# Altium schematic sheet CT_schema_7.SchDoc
size 274 x 160 mm
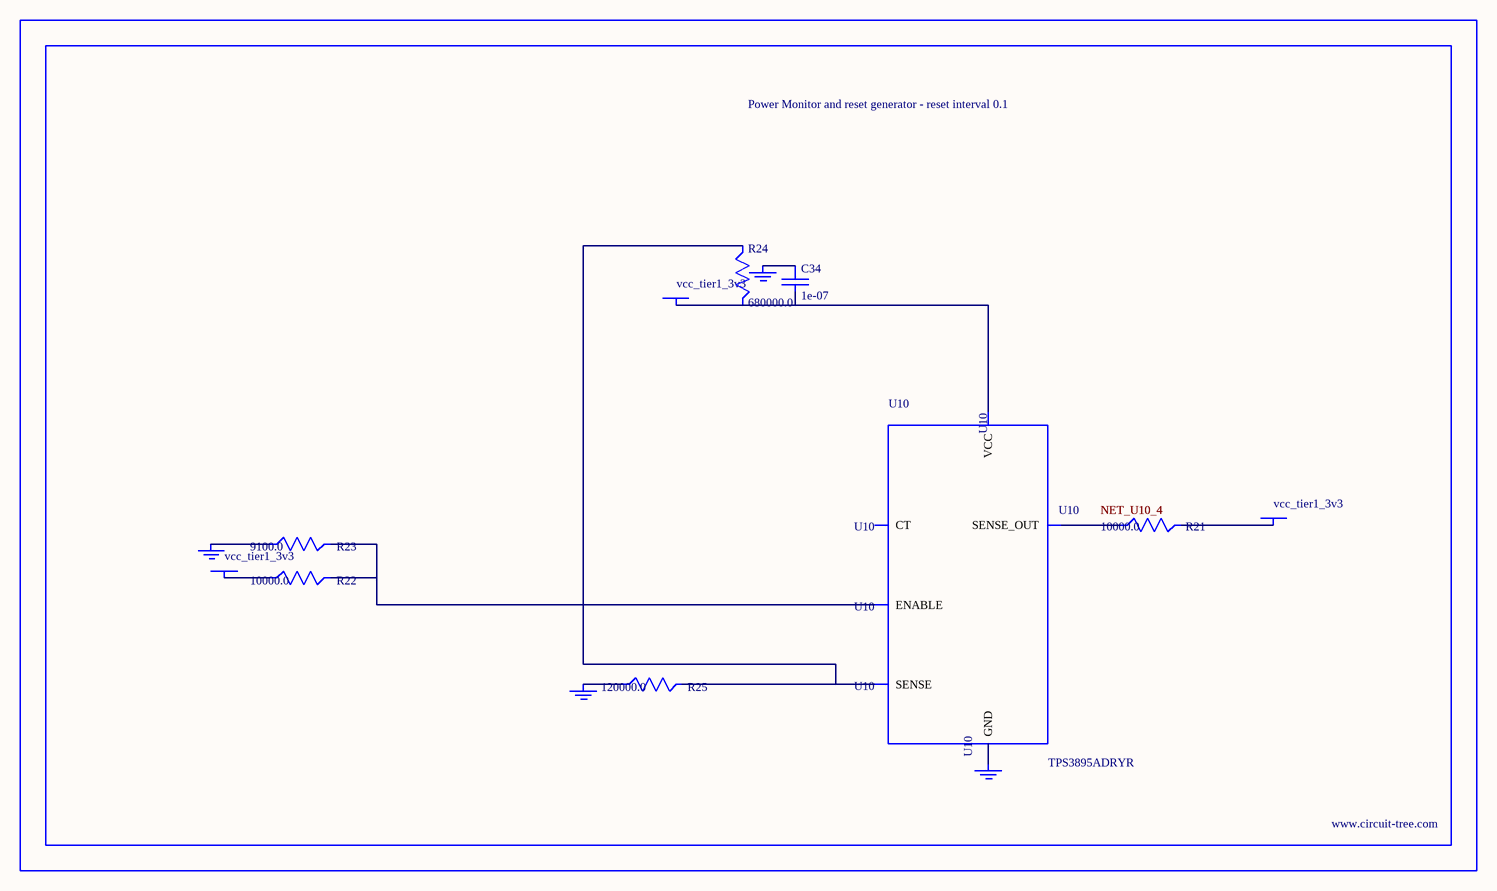
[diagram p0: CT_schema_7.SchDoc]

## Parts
BORDER6  (no value)
C34  1e-07  [C0402]
GND_INSTANCE_6_0  (no value)
GND_INSTANCE_6_1  (no value)
GND_INSTANCE_6_2  (no value)
GND_INSTANCE_6_3  (no value)
POWER_INSTANCE_6_0  vcc_tier1_3v3
POWER_INSTANCE_6_1  vcc_tier1_3v3
POWER_INSTANCE_6_2  vcc_tier1_3v3
R21  10000.0  [R0603]
R22  10000.0  [R0603]
R23  9100.0  [R0603]
R24  680000.0  [R0603]
R25  120000.0  [R0603]
U10  TPS3895ADRYR  [SON-6]

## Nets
NetC34_1: C34.1 GND_INSTANCE_6_2.0(GND)
NetC34_2: C34.2 POWER_INSTANCE_6_2.0(PWR) R24.2 U10.6(VCC)
NetGND_INSTANCE_6_0_0: GND_INSTANCE_6_0.0(GND) R23.1
NetGND_INSTANCE_6_1_0: GND_INSTANCE_6_1.0(GND) R25.1
NetGND_INSTANCE_6_3_0: GND_INSTANCE_6_3.0(GND) U10.2(GND)
NetPOWER_INSTANCE_6_0_0: POWER_INSTANCE_6_0.0(PWR) R22.1
NetPOWER_INSTANCE_6_1_0: POWER_INSTANCE_6_1.0(PWR) R21.2
NetR21_1: R21.1 U10.4(SENSE_OUT)
NetR22_2: R22.2 R23.2 U10.1(ENABLE)
NetR24_1: R24.1 R25.2 U10.3(SENSE)

Not connected (* = marked no-connect by the designer): U10 5(CT)

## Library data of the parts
BORDER6 = BORDER_PAGE6
C34 = C0402C104K3RACTU
GND_INSTANCE_6_0-GND_INSTANCE_6_3 = GND
POWER_INSTANCE_6_0-POWER_INSTANCE_6_2 = PWR
R21 R22 = RC0603JR-0710KL
R23 = RC0603JR-079K1L
R24 = RC0603JR-07680KL
R25 = RC0603JR-07120KL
